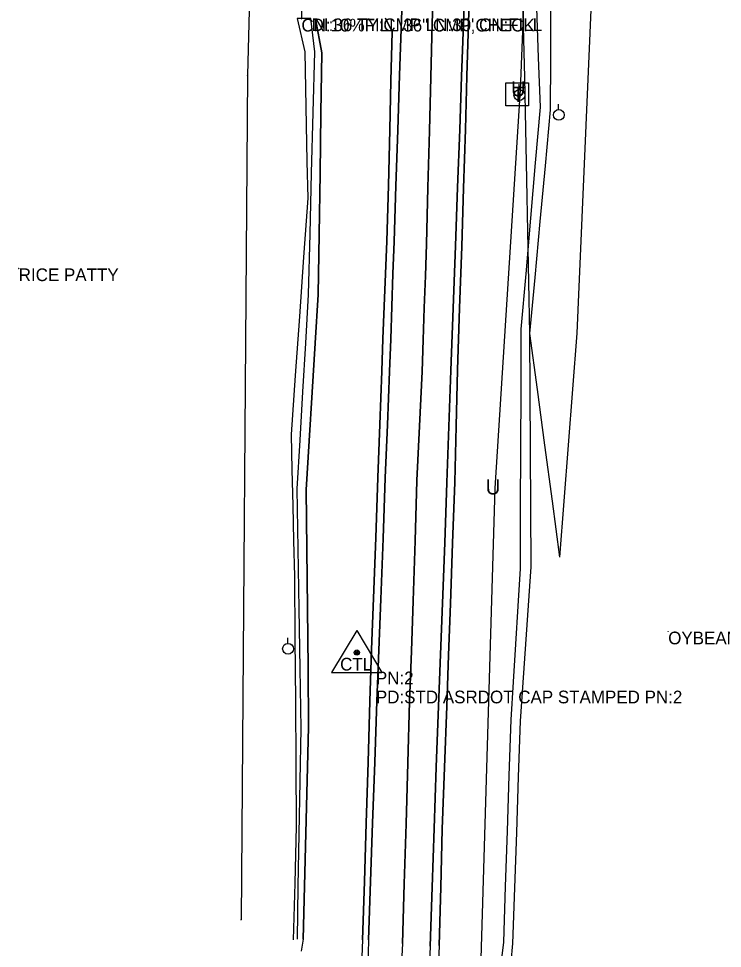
# Model space of a CAD drawing. Extents: x 1445297 to 1476720, y 2042269 to 2057889.
# Drawn here: x 1445911.7 to 1446189, y 2043033.6 to 2043399.8 of the extents above; entities that cross this region are included whole.
import ezdxf

# ---------------------------------------------------------------- set-up
doc = ezdxf.new("R2010")
doc.units = 0
for name, color, linetype in [('S_DITCHLINE', 7, 'Continuous'), ('S_DRG_PT_SYM', 7, 'Continuous'), ('S_EDGE_PAVEMENT', 7, 'Continuous'), ('S_MSC_PT_SYM', 7, 'Continuous'), ('S_PAVEMENT_CROWN', 7, 'Continuous'), ('S_PRIMARY_CTL', 7, 'Continuous'), ('S_PRIMARY_CTL_ANNOT', 7, 'Continuous'), ('S_SHOULDER', 7, 'Continuous'), ('S_SIDE_DRAIN', 7, 'Continuous'), ('S_SIDE_DRAIN_ANNOT', 7, 'Continuous'), ('S_SURVEY_TEXT_ANNOT', 7, 'Continuous'), ('S_TELEPHONE_UTILITIES', 7, 'Continuous'), ('S_TREE', 7, 'Continuous'), ('S_UNDERGROUND_CABLE', 7, 'Continuous'), ('S_UTILITY_POLE', 7, 'Continuous'), ('S_UTL_PT_SYM', 7, 'Continuous'), ('S_WATER_UTILITIES', 7, 'Continuous')]:
    doc.layers.add(name, color=color, linetype=linetype)

msp = doc.modelspace()

# ---------------------------------------------------------------- linework, layer by layer
at = {"layer": 'S_DITCHLINE'}
for points in [[(1446101.97, 2043028.57), (1446102.88, 2043036.01), (1446103.58, 2043057.92), (1446104.29, 2043079.83), (1446105, 2043101.75), (1446105.7, 2043123.66), (1446106.63, 2043138.56), (1446107.56, 2043153.47), (1446108.49, 2043168.37), (1446109.42, 2043183.28), (1446109.5, 2043206.82), (1446109.58, 2043230.35), (1446109.66, 2043253.89), (1446109.74, 2043277.43), (1446111.62, 2043299.3), (1446113.5, 2043321.17), (1446115.38, 2043343.03), (1446117.26, 2043364.9), (1446116.58, 2043384.46), (1446115.91, 2043404.02)], [(1446102.88, 2043036.01), (1446103.58, 2043057.92), (1446104.29, 2043079.83), (1446105, 2043101.75), (1446105.7, 2043123.66), (1446106.63, 2043138.56), (1446107.56, 2043153.47), (1446108.49, 2043168.37), (1446109.42, 2043183.28), (1446109.5, 2043206.82), (1446109.58, 2043230.35), (1446109.66, 2043253.89), (1446109.74, 2043277.43), (1446111.62, 2043299.3), (1446113.5, 2043321.17), (1446115.38, 2043343.03), (1446117.26, 2043364.9), (1446116.58, 2043384.46), (1446115.91, 2043404.02)], [(1446105.7, 2043028.12), (1446106.39, 2043035.48), (1446107.16, 2043057.39), (1446107.94, 2043079.31), (1446108.71, 2043101.22), (1446109.49, 2043123.14), (1446110.54, 2043138.31), (1446111.59, 2043153.48), (1446112.63, 2043168.65), (1446113.68, 2043183.82), (1446113.55, 2043206.82), (1446113.42, 2043229.82), (1446113.29, 2043252.82), (1446113.16, 2043275.83), (1446115.19, 2043297.84), (1446117.23, 2043319.86), (1446119.27, 2043341.88), (1446121.31, 2043363.9), (1446121.38, 2043383.66), (1446121.44, 2043403.41)], [(1446106.39, 2043035.48), (1446107.16, 2043057.39), (1446107.94, 2043079.31), (1446108.71, 2043101.22), (1446109.49, 2043123.14), (1446110.54, 2043138.31), (1446111.59, 2043153.48), (1446112.63, 2043168.65), (1446113.68, 2043183.82), (1446113.55, 2043206.82), (1446113.42, 2043229.82), (1446113.29, 2043252.82), (1446113.16, 2043275.83), (1446115.19, 2043297.84), (1446117.23, 2043319.86), (1446119.27, 2043341.88), (1446121.31, 2043363.9), (1446121.38, 2043383.66), (1446121.44, 2043403.41)], [(1446021.52, 2043037.21), (1446021.89, 2043057.95), (1446022.25, 2043078.7), (1446022.62, 2043099.44), (1446022.98, 2043120.19), (1446022.61, 2043143.8), (1446022.23, 2043167.4), (1446021.85, 2043191.01), (1446021.48, 2043214.62), (1446022.6, 2043233.74), (1446023.71, 2043252.85), (1446024.83, 2043271.97), (1446025.95, 2043291.08), (1446026.55, 2043314.98), (1446027.15, 2043338.88), (1446027.75, 2043362.78), (1446028.35, 2043386.67), (1446026.9, 2043399.8), (1446021.4, 2043399.8), (1446024.41, 2043386.66), (1446024.71, 2043372.27), (1446025.02, 2043357.87), (1446025.32, 2043343.48), (1446025.62, 2043329.09), (1446023.99, 2043305.81), (1446022.35, 2043282.54), (1446020.71, 2043259.26), (1446019.08, 2043235.99), (1446019.4, 2043222.03), (1446019.72, 2043208.07), (1446020.05, 2043194.11), (1446020.37, 2043180.15), (1446020.56, 2043155.54), (1446020.74, 2043130.93), (1446020.93, 2043106.32), (1446021.12, 2043081.71), (1446020.48, 2043059.33), (1446019.85, 2043037.03)], [(1446028.74, 2043399.78), (1446031.19, 2043386.38), (1446030.84, 2043362.57), (1446030.49, 2043338.76), (1446030.14, 2043314.94), (1446029.79, 2043291.13), (1446028.6, 2043271.91), (1446027.41, 2043252.69), (1446026.23, 2043233.48), (1446025.04, 2043214.26), (1446025.28, 2043190.88), (1446025.51, 2043167.49), (1446025.75, 2043144.11), (1446025.98, 2043120.73), (1446025.44, 2043099.87), (1446024.91, 2043079.01), (1446024.37, 2043058.16), (1446023.83, 2043037.3), (1446022.97, 2043032.53)], [(1446023.83, 2043037.3), (1446024.37, 2043058.16), (1446024.91, 2043079.01), (1446025.44, 2043099.87), (1446025.98, 2043120.73), (1446025.75, 2043144.11), (1446025.51, 2043167.49), (1446025.28, 2043190.88), (1446025.04, 2043214.26), (1446026.23, 2043233.48), (1446027.41, 2043252.69), (1446028.6, 2043271.91), (1446029.79, 2043291.13), (1446030.14, 2043314.94), (1446030.49, 2043338.76), (1446030.84, 2043362.57), (1446031.19, 2043386.38), (1446028.74, 2043399.78)]]:
    msp.add_lwpolyline(points, dxfattribs=at)
at = {"layer": 'S_DRG_PT_SYM'}
msp.add_lwpolyline([(1446023.13, 2043399.73), (1446023.13, 2043399.78), (1446023.13, 2043399.73), (1446023.08, 2043399.73), (1446023.13, 2043399.73), (1446023.13, 2043399.68), (1446023.13, 2043399.73), (1446023.18, 2043399.73)], dxfattribs=at)
at = {"layer": 'S_EDGE_PAVEMENT'}
for points in [[(1446063.21, 2043418.35), (1446062.55, 2043399.3), (1446061.81, 2043377.57), (1446061.08, 2043355.85), (1446060.36, 2043333.95), (1446059.65, 2043312.05), (1446059.2, 2043299.23), (1446058.76, 2043286.41), (1446058.31, 2043273.59), (1446057.86, 2043260.77), (1446057.02, 2043239.87), (1446056.18, 2043218.98), (1446055.28, 2043195.07), (1446054.39, 2043171.16), (1446053.64, 2043151.1), (1446052.89, 2043131.04), (1446052.04, 2043106.99), (1446051.18, 2043082.94), (1446050.38, 2043059.93), (1446049.58, 2043036.92), (1446049.31, 2043026.44)], [(1446049.58, 2043036.92), (1446050.38, 2043059.93), (1446051.18, 2043082.94), (1446052.04, 2043106.99), (1446052.89, 2043131.04), (1446053.64, 2043151.1), (1446054.39, 2043171.16), (1446055.28, 2043195.07), (1446056.18, 2043218.98), (1446057.02, 2043239.87), (1446057.86, 2043260.77), (1446058.31, 2043273.59), (1446058.76, 2043286.41), (1446059.2, 2043299.23), (1446059.65, 2043312.05), (1446060.36, 2043333.95), (1446061.08, 2043355.85), (1446061.81, 2043377.57), (1446062.55, 2043399.3), (1446063.21, 2043418.35)], [(1446087.69, 2043417.37), (1446087, 2043397.93), (1446086.25, 2043377.04), (1446085.5, 2043356.15), (1446084.67, 2043333.23), (1446083.84, 2043310.32), (1446082.92, 2043285.75), (1446081.99, 2043261.17), (1446081.23, 2043239.15), (1446080.46, 2043217.13), (1446079.57, 2043193.35), (1446078.67, 2043169.56), (1446077.91, 2043149.3), (1446077.14, 2043129.04), (1446076.25, 2043104.96), (1446075.37, 2043080.88), (1446074.61, 2043057.71), (1446073.85, 2043034.53), (1446073.51, 2043024.49)], [(1446073.85, 2043034.53), (1446074.61, 2043057.71), (1446075.37, 2043080.88), (1446076.25, 2043104.96), (1446077.14, 2043129.04), (1446077.91, 2043149.3), (1446078.67, 2043169.56), (1446079.57, 2043193.35), (1446080.46, 2043217.13), (1446081.23, 2043239.15), (1446081.99, 2043261.17), (1446082.92, 2043285.75), (1446083.84, 2043310.32), (1446084.67, 2043333.23), (1446085.5, 2043356.15), (1446086.25, 2043377.04), (1446087, 2043397.93), (1446087.69, 2043417.37)]]:
    msp.add_lwpolyline(points, dxfattribs=at)
at = {"layer": 'S_MSC_PT_SYM'}
for points in [[(1445911.75, 2043301.41), (1445911.75, 2043301.46), (1445911.75, 2043301.41), (1445911.7, 2043301.41), (1445911.75, 2043301.41), (1445911.75, 2043301.36), (1445911.75, 2043301.41), (1445911.8, 2043301.41)], [(1446167.63, 2043158.36), (1446167.63, 2043158.41), (1446167.63, 2043158.36), (1446167.58, 2043158.36), (1446167.63, 2043158.36), (1446167.63, 2043158.31), (1446167.63, 2043158.36), (1446167.68, 2043158.36)]]:
    msp.add_lwpolyline(points, dxfattribs=at)
at = {"layer": 'S_PAVEMENT_CROWN'}
for points in [[(1446075.25, 2043417.63), (1446074.6, 2043397.98), (1446074.08, 2043376.8), (1446073.55, 2043355.63), (1446072.99, 2043333.33), (1446072.43, 2043311.03), (1446071.99, 2043298.47), (1446071.54, 2043285.91), (1446071.09, 2043273.35), (1446070.64, 2043260.79), (1446069.61, 2043239.34), (1446068.57, 2043217.89), (1446067.88, 2043194.17), (1446067.19, 2043170.45), (1446066.45, 2043150.64), (1446065.71, 2043130.82), (1446065.06, 2043106.71), (1446064.4, 2043082.6), (1446063.65, 2043059.06), (1446062.89, 2043035.53), (1446062.44, 2043025.53)], [(1446062.89, 2043035.53), (1446063.65, 2043059.06), (1446064.4, 2043082.6), (1446065.06, 2043106.71), (1446065.71, 2043130.82), (1446066.45, 2043150.64), (1446067.19, 2043170.45), (1446067.88, 2043194.17), (1446068.57, 2043217.89), (1446069.61, 2043239.34), (1446070.64, 2043260.79), (1446071.09, 2043273.35), (1446071.54, 2043285.91), (1446071.99, 2043298.47), (1446072.43, 2043311.03), (1446072.99, 2043333.33), (1446073.55, 2043355.63), (1446074.08, 2043376.8), (1446074.6, 2043397.98), (1446075.25, 2043417.63)]]:
    msp.add_lwpolyline(points, dxfattribs=at)
at = {"layer": 'S_PRIMARY_CTL'}
for p, q in [((1446044.96, 2043158.82), (1446034.93, 2043142.3)), ((1446044.96, 2043158.82), (1446054.79, 2043142.3)), ((1446034.93, 2043142.3), (1446054.79, 2043142.3))]:
    msp.add_line(p, q, dxfattribs=at)
for radius in [1.04, 0.609, 0.344]:
    msp.add_circle((1446044.96, 2043150.12), radius, dxfattribs=at)
at = {"layer": 'S_SHOULDER'}
for points in [[(1446089.55, 2043418.22), (1446088.96, 2043398.24), (1446088.35, 2043377.19), (1446087.73, 2043356.14), (1446087.01, 2043333.07), (1446086.3, 2043310), (1446085.46, 2043285.71), (1446084.63, 2043261.42), (1446084.09, 2043239.31), (1446083.55, 2043217.21), (1446082.69, 2043193.25), (1446081.83, 2043169.29), (1446081.1, 2043149.13), (1446080.38, 2043128.97), (1446079.51, 2043104.79), (1446078.64, 2043080.62), (1446077.99, 2043057.68), (1446077.34, 2043034.74), (1446076.95, 2043024.75)], [(1446077.34, 2043034.74), (1446077.99, 2043057.68), (1446078.64, 2043080.62), (1446079.51, 2043104.79), (1446080.38, 2043128.97), (1446081.1, 2043149.13), (1446081.83, 2043169.29), (1446082.69, 2043193.25), (1446083.55, 2043217.21), (1446084.09, 2043239.31), (1446084.63, 2043261.42), (1446085.46, 2043285.71), (1446086.3, 2043310), (1446087.01, 2043333.07), (1446087.73, 2043356.14), (1446088.35, 2043377.19), (1446088.96, 2043398.24), (1446089.55, 2043418.22)], [(1446056.22, 2043399.99), (1446058.86, 2043394.66), (1446058.39, 2043375.33), (1446057.92, 2043355.99), (1446057.37, 2043334.07), (1446056.82, 2043312.14), (1446056.3, 2043299.33), (1446055.78, 2043286.52), (1446055.26, 2043273.71), (1446054.75, 2043260.9), (1446054.01, 2043240), (1446053.28, 2043219.11), (1446052.38, 2043195.33), (1446051.49, 2043171.55), (1446050.77, 2043151.26), (1446050.05, 2043130.98), (1446049.37, 2043106.94), (1446048.7, 2043082.91), (1446047.92, 2043059.94), (1446047.13, 2043036.97), (1446046.78, 2043026.92)], [(1446047.13, 2043036.97), (1446047.92, 2043059.94), (1446048.7, 2043082.91), (1446049.37, 2043106.94), (1446050.05, 2043130.98), (1446050.77, 2043151.26), (1446051.49, 2043171.55), (1446052.38, 2043195.33), (1446053.28, 2043219.11), (1446054.01, 2043240), (1446054.75, 2043260.9), (1446055.26, 2043273.71), (1446055.78, 2043286.52), (1446056.3, 2043299.33), (1446056.82, 2043312.14), (1446057.37, 2043334.07), (1446057.92, 2043355.99), (1446058.39, 2043375.33), (1446058.86, 2043394.66), (1446056.22, 2043399.99)]]:
    msp.add_lwpolyline(points, dxfattribs=at)
at = {"layer": 'S_SIDE_DRAIN'}
msp.add_line((1446023.04, 2043429.88), (1446023.13, 2043399.73), dxfattribs=at)
at = {"layer": 'S_TELEPHONE_UTILITIES'}
msp.add_lwpolyline([(1446103.62, 2043365.51), (1446103.62, 2043374.51), (1446112.62, 2043374.51), (1446112.62, 2043365.51)], close=True, dxfattribs=at)
at = {"layer": 'S_TREE'}
for points in [[(1446124.98, 2043187.67), (1446122.02, 2043209.71), (1446119.07, 2043231.75), (1446116.11, 2043253.79), (1446113.16, 2043275.83), (1446112.74, 2043295.98), (1446112.33, 2043316.14), (1446111.92, 2043336.29), (1446111.51, 2043356.45), (1446111.09, 2043376.6), (1446110.68, 2043396.76), (1446110.27, 2043416.91)], [(1446124.98, 2043187.67), (1446126.66, 2043209.73), (1446128.34, 2043231.8), (1446130.03, 2043253.86), (1446131.71, 2043275.92), (1446132.51, 2043294.11), (1446133.31, 2043312.3), (1446134.11, 2043330.49), (1446134.9, 2043348.69), (1446135.7, 2043366.88), (1446136.5, 2043385.07), (1446137.3, 2043403.26)]]:
    msp.add_lwpolyline(points, dxfattribs=at)
at = {"layer": 'S_UNDERGROUND_CABLE'}
for p, q in [((1446119.29, 2043617.64), (1446109.33, 2043371.71)), ((1446109.33, 2043371.71), (1446099.35, 2043214.92)), ((1446099.35, 2043214.92), (1446093.27, 2043011.34))]:
    msp.add_line(p, q, dxfattribs=at)
at = {"layer": 'S_UTILITY_POLE'}
for p, q in [((1446108.87, 2043371.84), (1446108.87, 2043373.95)), ((1446124.42, 2043364.01), (1446124.42, 2043366.12)), ((1446017.72, 2043153.75), (1446017.72, 2043155.86))]:
    msp.add_line(p, q, dxfattribs=at)
for centre in [(1446108.99, 2043369.7), (1446124.54, 2043361.87), (1446017.85, 2043151.61)]:
    msp.add_circle(centre, 2.13, dxfattribs=at)
at = {"layer": 'S_UTL_PT_SYM'}
for points in [[(1446001.92, 2043377.5), (1446001.92, 2043377.55), (1446001.92, 2043377.5), (1446001.86, 2043377.5), (1446001.92, 2043377.5), (1446001.92, 2043377.45), (1446001.92, 2043377.5), (1446001.97, 2043377.5)], [(1445999.37, 2043044.9), (1445999.37, 2043044.95), (1445999.37, 2043044.9), (1445999.32, 2043044.9), (1445999.37, 2043044.9), (1445999.37, 2043044.85), (1445999.37, 2043044.9), (1445999.42, 2043044.9)]]:
    msp.add_lwpolyline(points, dxfattribs=at)
at = {"layer": 'S_WATER_UTILITIES'}
for p, q in [((1446008.87, 2043640.47), (1446001.92, 2043377.5)), ((1446001.92, 2043377.5), (1445999.37, 2043044.9))]:
    msp.add_line(p, q, dxfattribs=at)

# ---------------------------------------------------------------- texts
at = {"layer": 'S_PRIMARY_CTL'}
msp.add_text('CTL', height=5, dxfattribs=at).set_placement((1446038.38, 2043143.04))
at = {"layer": 'S_PRIMARY_CTL_ANNOT'}
for s, p in [('PN:2', (1446052.46, 2043137.62)), ('PD:STD ASRDOT CAP STAMPED PN:2', (1446052.46, 2043130.12))]:
    msp.add_text(s, height=5, dxfattribs=at).set_placement(p)
at = {"layer": 'S_SIDE_DRAIN_ANNOT'}
for s, p in [('CN:10%FILL 36" CMP,CHECK', (1446023.13, 2043394.73)), ("DI:36 TY:CMP LN:30' CN:FILL", (1446027.16, 2043394.86))]:
    msp.add_text(s, height=5, dxfattribs=at).set_placement(p)
at = {"layer": 'S_SURVEY_TEXT_ANNOT'}
for s, p in [('RICE PATTY', (1445911.75, 2043296.41)), ('OYBEAN FIELD SOYBEAN FIELD', (1446167.63, 2043153.36))]:
    msp.add_text(s, height=5, dxfattribs=at).set_placement(p)
at = {"layer": 'S_TELEPHONE_UTILITIES'}
msp.add_text('T', height=6, dxfattribs=at).set_placement((1446106.18, 2043367.01))
at = {"layer": 'S_UTL_PT_SYM'}
for p in [(1446105.7, 2043369.16), (1446095.72, 2043212.38)]:
    msp.add_text('U', height=6, dxfattribs=at).set_placement(p)

doc.saveas('drawing.dxf')
